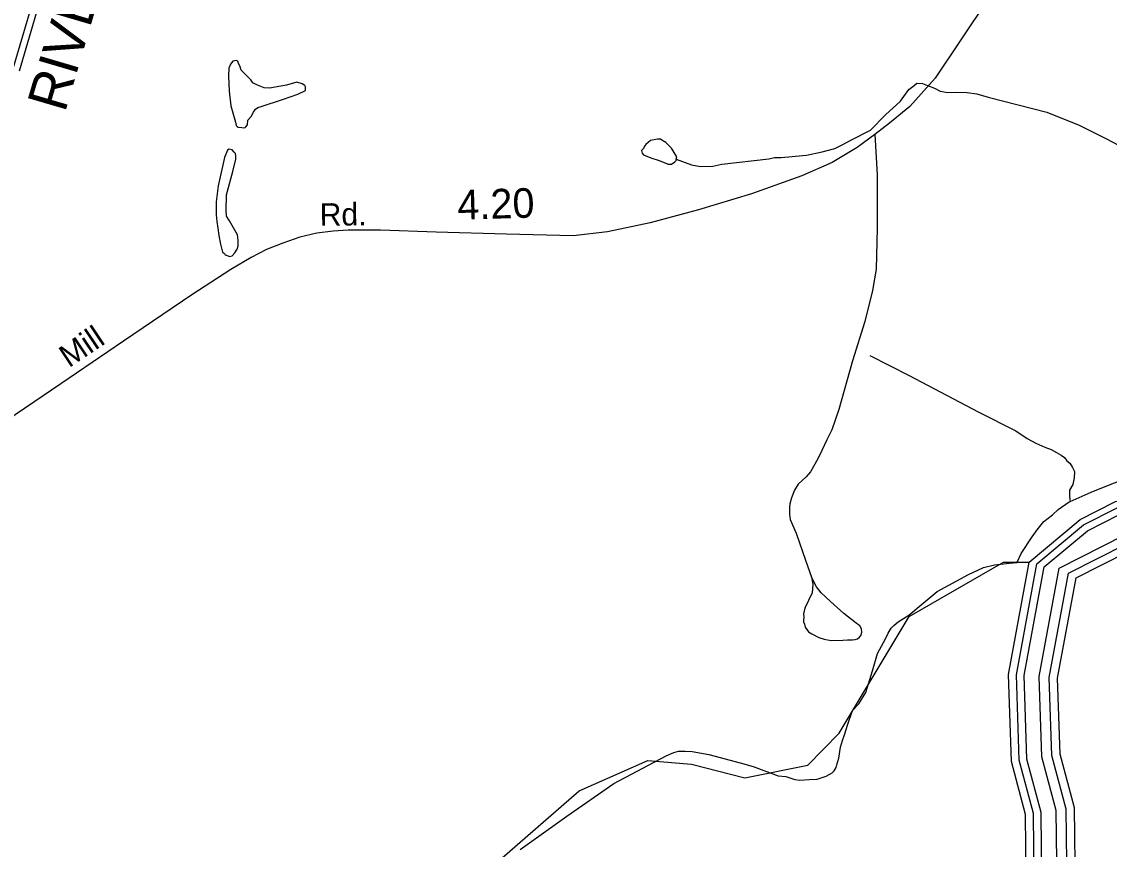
# Model space of a CAD drawing. Extents: x 2206922 to 2357709, y 510027 to 673830.
# Drawn here: x 2279953 to 2284540, y 588548 to 592040 of the extents above; entities that cross this region are included whole.
import ezdxf

# ---------------------------------------------------------------- set-up
doc = ezdxf.new("R2010")
doc.units = 0
for name, color, linetype in [('Exist Hydrographic Buffer Line', 7, 'Continuous'), ('Exist Hydrographic Misc Water Feature', 7, 'Continuous'), ('Exist Hydrographic River Shore', 7, 'Continuous'), ('Exist Hydrographic River Shore Label', 7, 'Continuous'), ('Exist Road Non-System Type 51', 7, 'Continuous'), ('Exist Road Secondary Mileage Hundredths English Label', 7, 'Continuous'), ('Exist Road Secondary Type 51 Attributed', 7, 'Continuous'), ('Exist Road Secondary Type 51 Label', 7, 'Continuous')]:
    doc.layers.add(name, color=color, linetype=linetype)

msp = doc.modelspace()

# ---------------------------------------------------------------- linework, layer by layer
at = {"layer": 'Exist Hydrographic Buffer Line'}
for points in [[(2279917.3, 591843.1), (2280038.9, 592257), (2280129.6, 592761.6)], [(2284233.9, 589752.2), (2284431.5, 589917), (2284572.7, 589988.6), (2285168.5, 590009.2), (2285562.9, 590073.9), (2285906.5, 590176.4), (2286250.3, 590341.9), (2286408.7, 590452.4)], [(2284264.6, 589740), (2284447.6, 589892.5), (2284580.1, 589959.8), (2285171.3, 589980.2), (2285569.4, 590045.5), (2285917, 590149.2), (2286265, 590316.7), (2286425.4, 590428.6)], [(2284328.3, 589734.2), (2284602.4, 589873.3), (2285179.9, 589893.2), (2285589, 589960.4), (2285948.6, 590067.6), (2286309.2, 590241.2), (2286475.3, 590357.1)], [(2284367, 589713), (2284611.7, 589837.2), (2285183.5, 589856.9), (2285597.2, 589924.8), (2285961.8, 590033.6), (2286327.6, 590209.6), (2286496.1, 590327.2)], [(2285107.8, 587521.9), (2284452.4, 587482.9), (2284212.4, 587550.4), (2284066.7, 587655.6), (2284003.1, 587841.1), (2284009.4, 587975.4), (2284222.9, 588411.5), (2284219.7, 588699.1), (2284159.8, 588923.6), (2284147.9, 589283.8), (2284233.9, 589752.2)], [(2285109.8, 587554.6), (2284455.9, 587515.7), (2284226.7, 587580.2), (2284094.1, 587675.9), (2284035.8, 587845.8), (2284041.6, 587967.2), (2284255.5, 588404.1), (2284252.2, 588703.5), (2284192.1, 588928.4), (2284180.5, 589281.4), (2284264.6, 589740)], [(2285113.8, 587618.6), (2284462.8, 587579.8), (2284254.8, 587638.4), (2284147.8, 587715.7), (2284100, 587855), (2284104.5, 587951), (2284319.3, 588389.7), (2284315.7, 588712.2), (2284255.5, 588937.8), (2284244.3, 589276.6), (2284328.3, 589734.2)], [(2285116.4, 587660.8), (2284467.4, 587622.1), (2284273.4, 587676.7), (2284183.1, 587741.9), (2284142.3, 587861), (2284146, 587940.4), (2284361.4, 588380.2), (2284357.6, 588717.9), (2284297.2, 588944), (2284286.4, 589273.5), (2284367, 589713)]]:
    msp.add_lwpolyline(points, dxfattribs=at)
at = {"layer": 'Exist Hydrographic Misc Water Feature'}
for points in [[(2280834.5, 591685.7), (2280855.2, 591616), (2280857.3, 591602), (2280861.2, 591598.1), (2280865.5, 591595.8), (2280881.5, 591594.3), (2280893.4, 591592.4), (2280897.5, 591596.3), (2280905.3, 591604.5), (2280906.9, 591624.5), (2280921, 591640.6), (2280930.7, 591658.6), (2280938.7, 591670.8), (2280948.5, 591678.6), (2280962.5, 591683), (2281052.3, 591711.7), (2281118.1, 591734.2), (2281149.7, 591750.5), (2281149.9, 591756.6), (2281149.9, 591764.7), (2281147.4, 591770.7), (2281135.7, 591778.6), (2281113.2, 591784.4), (2281069.9, 591771.9), (2280997.7, 591759.2), (2280975.8, 591760.9), (2280947.7, 591772.8), (2280927.6, 591782.4), (2280919.4, 591794.6), (2280879, 591835.9), (2280872.7, 591853.9), (2280866.7, 591863.7), (2280864.7, 591873.8), (2280856.9, 591875.8), (2280842.9, 591873.8), (2280832.9, 591861.5), (2280826.7, 591843.4), (2280825.3, 591811.5), (2280827.7, 591747.5), (2280834.5, 591685.7)], [(2282713.4, 591459.4), (2282777.8, 591435.9), (2282815.7, 591428.5), (2282868, 591430.8), (2282905.9, 591439.3), (2283103.4, 591461), (2283127.4, 591467.2), (2283155.5, 591467.4), (2283263.1, 591476.7), (2283329, 591491.1), (2283382.7, 591505.7), (2283412.8, 591519.9), (2283452.6, 591542.2), (2283532.2, 591583), (2283595.5, 591647.6), (2283658.5, 591704.3), (2283694.2, 591754.5), (2283716.3, 591770.6), (2283728.2, 591780.6), (2283752.2, 591779), (2283773.7, 591771.2), (2283802.4, 591759.2), (2283826.4, 591747.5), (2283858.2, 591741.9), (2283890.2, 591742.4), (2283940.4, 591740.9), (2283980.4, 591735.3), (2284028.2, 591721.6), (2284276.9, 591658.2), (2284413.1, 591603.1), (2284527.7, 591546.1), (2284605.8, 591505.2)], [(2282713.4, 591459.4), (2282715.5, 591469.6), (2282693.1, 591507), (2282669.1, 591530.9), (2282652.9, 591540.7), (2282646.8, 591544.9), (2282634.9, 591544.6), (2282604.9, 591538.2), (2282585.2, 591522.1), (2282581.1, 591516.2), (2282573.4, 591504), (2282567.2, 591496), (2282569.5, 591485.9), (2282575.4, 591478.2), (2282605.8, 591466.3), (2282641.6, 591454.8), (2282679.8, 591439.3), (2282693.7, 591439.2), (2282707.9, 591449.3), (2282713.8, 591455.3), (2282713.4, 591459.4)], [(2280791.7, 591101.6), (2280800.1, 591067.6), (2280808.5, 591061.8), (2280810.5, 591055.9), (2280830.4, 591050), (2280840.5, 591052.2), (2280852.1, 591064.2), (2280862.2, 591080.5), (2280865.7, 591094.2), (2280865.5, 591118.5), (2280863.6, 591140.3), (2280829, 591199.9), (2280816.9, 591219.9), (2280814.6, 591243.8), (2280816.3, 591309.7), (2280843.1, 591407.8), (2280856.5, 591460.1), (2280856.2, 591474), (2280854.6, 591484), (2280848.3, 591490.2), (2280840.3, 591499.9), (2280828.2, 591501.7), (2280820.2, 591497.6), (2280808.5, 591467.4), (2280781.6, 591347.3), (2280772.4, 591279.4), (2280772.8, 591225.3), (2280775.5, 591197.4), (2280779.8, 591169.6), (2280783.7, 591137.4), (2280791.7, 591101.6)], [(2284374.1, 590015.7), (2284463.9, 590054.5), (2284557, 590093.6), (2284645, 590124.1), (2284688.9, 590132.5), (2284828.7, 590150), (2284956.7, 590165.2), (2285088.1, 590174.1), (2285264.3, 590172), (2285373.8, 590189.2), (2285516.1, 590206.2), (2285615.7, 590215.1), (2285703.5, 590242.1), (2285837, 590293.3), (2285999.8, 590362.9), (2286139.2, 590442), (2286268.6, 590511.4), (2286370.3, 590566.2), (2286467.3, 590635.1), (2286521.2, 590675.7)], [(2283529.3, 590631.7), (2283695.4, 590547), (2283986.6, 590394.1), (2284145.3, 590313.4), (2284193.7, 590281.7), (2284229.8, 590262.1), (2284268.1, 590244.6), (2284294.2, 590235), (2284316.5, 590223.1), (2284336.6, 590211.2), (2284350.5, 590201.3), (2284360.6, 590187.7), (2284372.7, 590177.7), (2284385, 590159.7), (2284393, 590141.8), (2284391.1, 590115.8), (2284385.8, 590087.8), (2284371.9, 590063.9), (2284372.1, 590039.5), (2284373.7, 590023.9), (2284374.1, 590015.7)], [(2284151, 589757.7), (2284152.5, 589762), (2284168.5, 589796.1), (2284213.8, 589866.3), (2284235.3, 589896.7), (2284263, 589930.6), (2284300.5, 589959.1), (2284324.7, 589981.4), (2284370.4, 590013.8), (2284374.1, 590015.7)], [(2277260.7, 586614.5), (2277653.7, 586377), (2278171.7, 586189.4), (2278796.7, 586203), (2279660.8, 586421.6), (2279884.7, 586538.4), (2280064.7, 586839.7), (2280270.6, 587075), (2281014.8, 587673.2), (2282303.7, 588795), (2282593.7, 588923.5), (2282777.8, 588906.7), (2283002.7, 588849.7), (2283268.7, 588903.3), (2283400.7, 589038.4), (2283695.8, 589530.9), (2284093.8, 589759), (2284201.7, 589760)], [(2282055, 588546.7), (2282065.4, 588554.8), (2282251.6, 588688.6), (2282450.5, 588826.5), (2282671.4, 588942.5), (2282703.2, 588956.8), (2282723.2, 588962.7), (2282750.9, 588962.9), (2282781.1, 588961.3), (2282850.8, 588947.9), (2282983.3, 588913.4), (2283037.6, 588897.9), (2283071.4, 588884.3), (2283110, 588870.4), (2283143.6, 588858.8), (2283175.8, 588855.1), (2283213.7, 588843.4), (2283234, 588839.5), (2283275.7, 588842.1), (2283307.9, 588844.2), (2283345.6, 588856.7), (2283371.4, 588871.1), (2283379.6, 588879.2), (2283387.4, 588893), (2283391.1, 588905), (2283399.1, 588933), (2283406.5, 588979.4), (2283414.5, 589007.3), (2283423.9, 589035.5), (2283435.8, 589071.5), (2283456.7, 589133.6), (2283482.8, 589161.7), (2283512.3, 589210), (2283541, 589300.6), (2283562.7, 589374.7), (2283595.9, 589436.6), (2283607.6, 589460.8), (2283619.5, 589481), (2283631.2, 589493), (2283649.5, 589507.3), (2283695, 589535.7), (2283754.5, 589586.4), (2283813.7, 589636.6), (2283945.6, 589708), (2284008.9, 589736.6), (2284055.3, 589749.1), (2284118.6, 589755.3), (2284151, 589757.7)]]:
    msp.add_lwpolyline(points, dxfattribs=at)
at = {"layer": 'Exist Hydrographic River Shore'}
for points in [[(2279943.7, 591833.2), (2280066.3, 592250.6), (2280155.8, 592748.4)], [(2284201.7, 589760), (2284416.8, 589939.4), (2284565.8, 590015), (2285165.8, 590035.7), (2285556.9, 590099.9), (2285896.8, 590201.3), (2286236.8, 590364.9), (2286393.5, 590474.3)], [(2284399.4, 589693.3), (2284619.9, 589805.2), (2285186.7, 589824.8), (2285604.4, 589893.3), (2285973.4, 590003.4), (2286343.9, 590181.7), (2286514.5, 590300.8)], [(2285105.7, 587488.7), (2284448.8, 587449.6), (2284197.8, 587520.2), (2284038.9, 587634.9), (2283969.8, 587836.4), (2283976.7, 587983.8), (2284189.8, 588418.9), (2284186.7, 588694.5), (2284126.8, 588918.8), (2284114.7, 589286.3), (2284201.7, 589760)], [(2285118.6, 587696.3), (2284471.2, 587657.8), (2284289, 587709.1), (2284212.9, 587764), (2284177.9, 587866.1), (2284181, 587931.4), (2284396.8, 588372.2), (2284392.9, 588722.8), (2284332.5, 588949.2), (2284321.9, 589270.8), (2284399.4, 589693.3)]]:
    msp.add_lwpolyline(points, dxfattribs=at)
at = {"layer": 'Exist Road Non-System Type 51'}
for points in [[(2283550.4, 591563.9), (2283561.3, 591393.5), (2283561.1, 591169), (2283556.2, 590995.4), (2283541.3, 590906.2), (2283508.3, 590775.6), (2283457.1, 590608.7), (2283399.3, 590403.8), (2283369.2, 590317.6), (2283348.2, 590275.6), (2283327.3, 590230.2), (2283311.5, 590198.7), (2283297.6, 590172.5), (2283280.1, 590141), (2283260.9, 590120), (2283227.7, 590088.6), (2283212, 590064.1), (2283199.7, 590030.9), (2283192.8, 590006.4), (2283191, 589990.7), (2283191, 589962.7), (2283194.5, 589940), (2283219, 589882.3), (2283259.1, 589768.7), (2283283.6, 589697)], [(2283283.6, 589697), (2283288.8, 589667.3), (2283286.1, 589630.9), (2283271.4, 589597.4), (2283255.6, 589565.9), (2283250.4, 589541.5), (2283252.1, 589529.2), (2283250.4, 589513.5), (2283250.4, 589508.3), (2283253.9, 589497.8), (2283257.4, 589485.5), (2283271.4, 589466.3), (2283285.3, 589457.6), (2283315, 589441.8), (2283337.7, 589434.8), (2283367.4, 589429.6), (2283416.5, 589430.4), (2283435.6, 589431.3), (2283456.5, 589431.3), (2283467.7, 589433.6), (2283478.4, 589436.8), (2283486.2, 589443.6), (2283493.2, 589452.3), (2283496.7, 589464.6), (2283495, 589478.5), (2283488, 589490.8), (2283472.3, 589503), (2283419.9, 589543.2), (2283364, 589593.9), (2283324.4, 589629.8), (2283305.5, 589656.2), (2283283.6, 589697)]]:
    msp.add_lwpolyline(points, dxfattribs=at)
at = {"layer": 'Exist Road Secondary Type 51 Attributed'}
msp.add_lwpolyline([(2284024.4, 592129.1), (2283804.8, 591801.9), (2283699, 591682.9), (2283613.2, 591611.9), (2283550.4, 591563.9), (2283476.1, 591509.4), (2283370.4, 591446.6), (2283243.2, 591390.4), (2283031.1, 591313.5), (2282806.7, 591246.4), (2282603.3, 591191.8), (2282423, 591154), (2282279.3, 591137.3), (2281997.3, 591143.5), (2281700.6, 591151.9), (2281465.7, 591160.3), (2281329.4, 591160.3), (2281266.5, 591156.1), (2281197.3, 591147.7), (2281126, 591131), (2281054.7, 591105.8), (2280985.5, 591078.5), (2280920.5, 591044.9), (2280834.5, 590994.6), (2280669.9, 590887.6), (2280382.6, 590692.4), (2280117.3, 590512), (2279770.1, 590276.7)], dxfattribs=at)

# ---------------------------------------------------------------- texts
at = {"layer": 'Exist Hydrographic River Shore Label'}
msp.add_text('RIVER', height=167.32, rotation=73.632, dxfattribs=at).set_placement((2280135, 591652.8))
at = {"layer": 'Exist Road Secondary Mileage Hundredths English Label'}
msp.add_text('4.20', height=125, rotation=1.6797, dxfattribs=at).set_placement((2281792, 591204.4))
at = {"layer": 'Exist Road Secondary Type 51 Label'}
for s, rotation, p in [('Rd.', 0.535, (2281209.9, 591179)), ('Mill', 33.8565, (2280152.4, 590577.9))]:
    msp.add_text(s, height=95, rotation=rotation, dxfattribs=at).set_placement(p)

doc.saveas('drawing.dxf')
